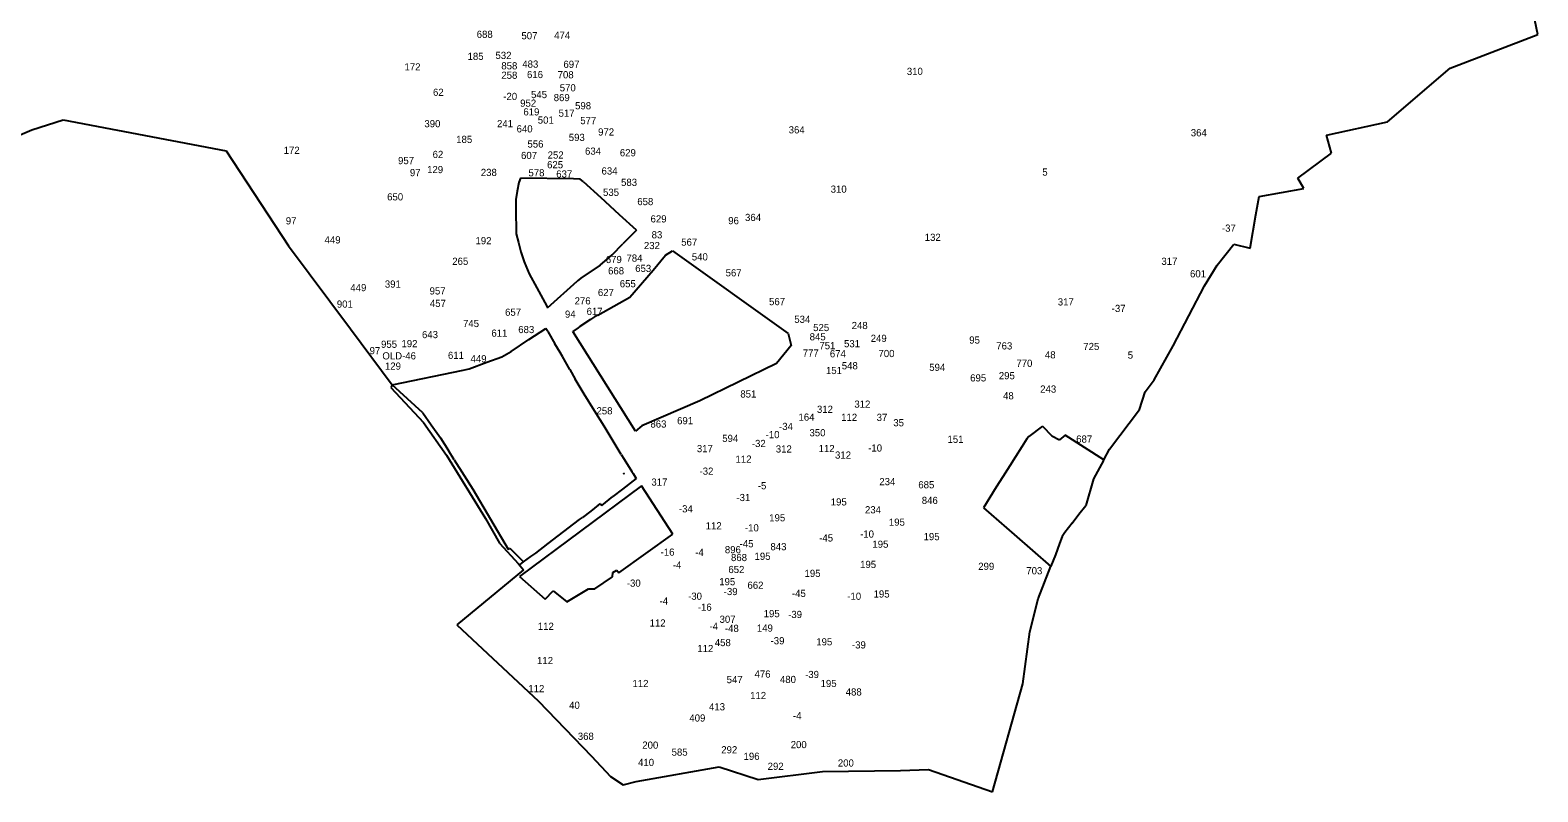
# Model space of a CAD drawing. Extents: x -782977 to -778030, y -975420 to -964838.
# Drawn here: x -780729 to -779276, y -975420 to -974686 of the extents above; entities that cross this region are included whole.
import ezdxf

# ---------------------------------------------------------------- set-up
doc = ezdxf.new("R2010")
doc.units = 0
for name, color, linetype in [('Vrstva 13', 7, 'Continuous'), ('Vrstva 24', 7, 'Continuous'), ('Vrstva 25', 7, 'Continuous')]:
    doc.layers.add(name, color=color, linetype=linetype)

msp = doc.modelspace()

# ---------------------------------------------------------------- linework, layer by layer
at = {"layer": 'Vrstva 13'}
for p, q in [((-779276.15, -974689.93), (-779291.56, -974614.39)), ((-779360.76, -974722.48), (-779276.15, -974689.93)), ((-779420.96, -974774.16), (-779360.76, -974722.48)), ((-780727.54, -974781.83), (-780697.45, -974772.06)), ((-780697.45, -974772.06), (-780540.25, -974801.96)), ((-779479.96, -974787.01), (-779420.96, -974774.16)), ((-780777.37, -974803.19), (-780727.54, -974781.83)), ((-779474.98, -974804.25), (-779479.96, -974787.01)), ((-780540.25, -974801.96), (-780480.25, -974893.51)), ((-779507.54, -974828.24), (-779474.98, -974804.25)), ((-780258.12, -974832.52), (-780260.02, -974840.79)), ((-780256.54, -974828.45), (-780258.12, -974832.52)), ((-780205.46, -974828.92), (-780256.54, -974828.45)), ((-780199.25, -974829.28), (-780205.46, -974828.92)), ((-780196.16, -974831.59), (-780199.25, -974829.28)), ((-780196.16, -974831.59), (-780179.25, -974847.09)), ((-779501.54, -974838.41), (-779507.54, -974828.24)), ((-780261.05, -974848.88), (-780261.22, -974856.8)), ((-780260.02, -974840.79), (-780261.05, -974848.88)), ((-780161.32, -974863.73), (-780179.25, -974847.09)), ((-779548.05, -974863.78), (-779544.88, -974845.91)), ((-779544.88, -974845.91), (-779501.54, -974838.41)), ((-780261.22, -974856.8), (-780261.22, -974865.41)), ((-780144.95, -974878.55), (-780161.32, -974863.73)), ((-779553.44, -974895.73), (-779548.05, -974863.78)), ((-780261.22, -974865.41), (-780260.88, -974874.37)), ((-780260.88, -974874.37), (-780260.71, -974881.95)), ((-780144.95, -974878.55), (-780158.07, -974891.81)), ((-780260.71, -974881.95), (-780258.47, -974890.39)), ((-780258.47, -974890.39), (-780256.23, -974899.51)), ((-780168.47, -974902.2), (-780158.07, -974891.81)), ((-779585.17, -974912.21), (-779569.2, -974891.86)), ((-779569.2, -974891.86), (-779553.44, -974895.73)), ((-780480.25, -974893.51), (-780420.62, -974973.73)), ((-780256.23, -974899.51), (-780253.04, -974909.11)), ((-780179.77, -974912.08), (-780168.47, -974902.2)), ((-780128.94, -974917.07), (-780116.94, -974902.63)), ((-780116.94, -974902.63), (-780110.08, -974898.35)), ((-780110.08, -974898.35), (-779998.78, -974978.05)), ((-780253.04, -974909.11), (-780248.26, -974920.44)), ((-780248.26, -974920.44), (-780241.08, -974933.98)), ((-780179.77, -974912.08), (-780198.49, -974924.83)), ((-780151.43, -974943.18), (-780128.94, -974917.07)), ((-779597.43, -974931.99), (-779585.17, -974912.21)), ((-780241.08, -974933.98), (-780231.26, -974951.83)), ((-780230.57, -974953.29), (-780202.19, -974927.69)), ((-780198.49, -974924.83), (-780202.19, -974927.69)), ((-779627.7, -974989.87), (-779597.43, -974931.99)), ((-780182.13, -974960.29), (-780151.43, -974943.18)), ((-780231.26, -974951.83), (-780230.57, -974953.29)), ((-780189.22, -974964.57), (-780199.35, -974971.3)), ((-780185.39, -974961.96), (-780189.22, -974964.57)), ((-780182.13, -974960.29), (-780185.39, -974961.96)), ((-780420.62, -974973.73), (-780380.36, -975027.54)), ((-780248.66, -974983.75), (-780232.22, -974973.26)), ((-780230.35, -974976.24), (-780232.22, -974973.26)), ((-780230.35, -974976.24), (-780223.44, -974988.04)), ((-780201.16, -974972.53), (-780206.256, -974976.114)), ((-780145.705, -975072.215), (-780206.256, -974976.114)), ((-780199.35, -974971.3), (-780201.16, -974972.53)), ((-779998.78, -974978.05), (-779995.86, -974989.73)), ((-780265.82, -974995.34), (-780248.66, -974983.75)), ((-780218.56, -974996.55), (-780223.44, -974988.04)), ((-779995.86, -974989.73), (-780009.85, -975007.08)), ((-779645.81, -975022.66), (-779627.7, -974989.87)), ((-780306.23, -975011.99), (-780289.25, -975005.87)), ((-780289.25, -975005.87), (-780274.5, -975000.49)), ((-780274.5, -975000.49), (-780265.82, -974995.34)), ((-780216.18, -975000.27), (-780218.56, -974996.55)), ((-780209.04, -975012.94), (-780216.18, -975000.27)), ((-780009.85, -975007.08), (-780083.92, -975043)), ((-780380.36, -975027.54), (-780311.78, -975013.35)), ((-780311.78, -975013.35), (-780306.23, -975011.99)), ((-780209.04, -975012.94), (-780203.9, -975022.23)), ((-780195.28, -975036.66), (-780203.9, -975022.23)), ((-779654.66, -975034.31), (-779645.81, -975022.66)), ((-780380.36, -975027.54), (-780381.79, -975029.98)), ((-780381.79, -975029.98), (-780350.26, -975063.75)), ((-780350.81, -975054.67), (-780380.36, -975027.54)), ((-780185.48, -975052.71), (-780195.28, -975036.66)), ((-779660.17, -975051.23), (-779654.66, -975034.31)), ((-780176.19, -975067.31), (-780185.48, -975052.71)), ((-780083.92, -975043), (-780139.82, -975067.22)), ((-779689.15, -975089.58), (-779660.17, -975051.23)), ((-780350.81, -975054.67), (-780342.75, -975066.05)), ((-780350.26, -975063.75), (-780328.05, -975095.44)), ((-780342.75, -975066.05), (-780333.77, -975078.61)), ((-780159.53, -975094.59), (-780176.19, -975067.31)), ((-780139.82, -975067.22), (-780145.705, -975072.215)), ((-779753.47, -975067.41), (-779766.6, -975077.49)), ((-779753.47, -975067.41), (-779744.49, -975076.59)), ((-780333.77, -975078.61), (-780326.02, -975091.01)), ((-779768.69, -975079.53), (-779773.57, -975087.26)), ((-779766.6, -975077.49), (-779768.69, -975079.53)), ((-779744.49, -975076.59), (-779737.19, -975080.54)), ((-779731.85, -975076.16), (-779737.19, -975080.54)), ((-779694.586, -975099.942), (-779731.85, -975076.16)), ((-780328.05, -975095.44), (-780290.43, -975156.47)), ((-780320.51, -975099.89), (-780326.02, -975091.01)), ((-780159.53, -975094.59), (-780156.63, -975099.15)), ((-779773.57, -975087.26), (-779779.53, -975097.04)), ((-779694.586, -975099.942), (-779689.15, -975089.58)), ((-780320.51, -975099.89), (-780311.12, -975114.84)), ((-780156.63, -975099.15), (-780149.21, -975111.17)), ((-780149.21, -975111.17), (-780148.01, -975113.1)), ((-779785.07, -975105.8), (-779791.79, -975116.39)), ((-779779.53, -975097.04), (-779785.07, -975105.8)), ((-779694.78, -975100.37), (-779704.54, -975118.21)), ((-779694.78, -975100.37), (-779693.82, -975098.61)), ((-780311.12, -975114.84), (-780302.5, -975128.1)), ((-780140.16, -975125.02), (-780257.48, -975212.39)), ((-780145.18, -975117.69), (-780158.48, -975128.11)), ((-780148.01, -975113.1), (-780145.18, -975117.69)), ((-780109.97, -975171.36), (-780140.16, -975125.02)), ((-779791.79, -975116.39), (-779798.1, -975126.17)), ((-779704.54, -975118.21), (-779711.67, -975143.72)), ((-780302.5, -975128.1), (-780268.63, -975185.97)), ((-780178.23, -975143.92), (-780167.57, -975135.33)), ((-780158.48, -975128.11), (-780167.57, -975135.33)), ((-779804.2, -975136.09), (-779810.51, -975146.08)), ((-779798.1, -975126.17), (-779804.2, -975136.09)), ((-780188.78, -975149.25), (-780196.9, -975155.33)), ((-780181.69, -975143.64), (-780188.78, -975149.25)), ((-780179.65, -975142.22), (-780181.69, -975143.64)), ((-780179.65, -975142.22), (-780178.23, -975143.92)), ((-779810.51, -975146.08), (-779781.02, -975171.97)), ((-779725.13, -975160.88), (-779718.54, -975152.19)), ((-779718.54, -975152.19), (-779711.67, -975143.72)), ((-780290.43, -975156.47), (-780276.8, -975180.07)), ((-780220.42, -975173.08), (-780199.79, -975157.42)), ((-780199.79, -975157.42), (-780196.9, -975155.33)), ((-779725.13, -975160.88), (-779732.15, -975169.96)), ((-780276.8, -975180.07), (-780258.5, -975200.01)), ((-780241.82, -975189.73), (-780229.93, -975180.44)), ((-780229.93, -975180.44), (-780220.42, -975173.08)), ((-780161.99, -975208.72), (-780109.97, -975171.36)), ((-779781.02, -975171.97), (-779745.6, -975202.52)), ((-779737.14, -975180.6), (-779741.02, -975191.34)), ((-779734.46, -975173.8), (-779737.14, -975180.6)), ((-779732.15, -975169.96), (-779734.46, -975173.8)), ((-780268.63, -975185.97), (-780266.82, -975185.06)), ((-780266.82, -975185.06), (-780253.83, -975198.23)), ((-780257.11, -975200.61), (-780253.83, -975198.23)), ((-780253.83, -975198.23), (-780246.58, -975193.13)), ((-780246.58, -975193.13), (-780241.82, -975189.73)), ((-779741.02, -975191.34), (-779745.47, -975202.4)), ((-780253.63, -975205.91), (-780317.9, -975259.01)), ((-780258.5, -975200.01), (-780253.63, -975205.91)), ((-780257.48, -975212.39), (-780232.85, -975234.28)), ((-780185.02, -975224.25), (-780167.91, -975212.49)), ((-780167.91, -975212.49), (-780167.71, -975208.41)), ((-780167.71, -975208.41), (-780163.73, -975206.27)), ((-780163.73, -975206.27), (-780161.99, -975208.72)), ((-779757.88, -975233.93), (-779745.47, -975202.4)), ((-780232.85, -975234.28), (-780225.3, -975226.22)), ((-780225.3, -975226.22), (-780212.14, -975236.73)), ((-780212.14, -975236.73), (-780190.99, -975224.05)), ((-780190.99, -975224.05), (-780185.02, -975224.25)), ((-779765.71, -975265.56), (-779757.88, -975233.93)), ((-780317.9, -975259.01), (-780239.2, -975332.45)), ((-779772.57, -975315.67), (-779765.71, -975265.56)), ((-779801.7, -975419.88), (-779772.57, -975315.67)), ((-780239.2, -975332.45), (-780188.15, -975385.55)), ((-780188.15, -975385.55), (-780170.05, -975405.08)), ((-780145.24, -975409.97), (-780065.11, -975395.72)), ((-780065.11, -975395.72), (-780027.71, -975407.86)), ((-780027.71, -975407.86), (-779965.66, -975400.41)), ((-779965.66, -975400.41), (-779890.42, -975399.39)), ((-779890.42, -975399.39), (-779863.52, -975398.32)), ((-779863.52, -975398.32), (-779801.7, -975419.88)), ((-780170.05, -975405.08), (-780157.64, -975413.22)), ((-780157.64, -975413.22), (-780145.24, -975409.97))]:
    msp.add_line(p, q, dxfattribs=at)
at = {"layer": 'Vrstva 25'}
msp.add_circle((-780157.03, -975113.05), 0.175, dxfattribs=at)

# ---------------------------------------------------------------- texts
at = {"layer": 'Vrstva 24'}
for s, p in [('688', (-780298.869, -974693.162)), ('507', (-780255.771, -974694.492)), ('474', (-780224.205, -974694.102)), ('172', (-780368.482, -974724.572)), ('185', (-780307.675, -974714.382)), ('532', (-780280.782, -974713.462)), ('858', (-780275.142, -974723.532)), ('483', (-780254.925, -974721.862)), ('697', (-780215.281, -974722.062)), ('258', (-780275.132, -974732.602)), ('616', (-780250.389, -974731.942)), ('708', (-780220.861, -974732.132)), ('310', (-779884.308, -974728.872)), ('62', (-780341.003, -974749.032)), ('-20', (-780273.279, -974753.015)), ('545', (-780246.525, -974751.232)), ('869', (-780224.665, -974754.122)), ('570', (-780218.841, -974744.712)), ('952', (-780256.999, -974759.492)), ('619', (-780253.909, -974767.912)), ('517', (-780219.953, -974769.152)), ('598', (-780204.069, -974761.992)), ('390', (-780349.281, -974779.292)), ('241', (-780279.288, -974779.282)), ('501', (-780240.007, -974775.802)), ('577', (-780199.055, -974776.322)), ('185', (-780318.625, -974794.442)), ('640', (-780260.414, -974784.272)), ('593', (-780210.129, -974792.522)), ('972', (-780181.855, -974787.282)), ('364', (-779998.201, -974785.232)), ('364', (-779610.621, -974788.012)), ('172', (-780484.932, -974804.942)), ('62', (-780341.363, -974808.922)), ('607', (-780256.147, -974809.912)), ('556', (-780249.959, -974798.862)), ('252', (-780230.512, -974809.512)), ('634', (-780194.481, -974805.762)), ('629', (-780160.925, -974807.282)), ('957', (-780374.685, -974814.872)), ('97', (-780363.269, -974826.482)), ('129', (-780346.662, -974823.522)), ('238', (-780294.912, -974826.272)), ('578', (-780248.999, -974826.632)), ('625', (-780231.029, -974818.812)), ('637', (-780222.235, -974827.772)), ('634', (-780178.561, -974824.862)), ('5', (-779753.75, -974825.952)), ('583', (-780159.742, -974835.822)), ('310', (-779957.718, -974842.382)), ('650', (-780385.191, -974849.812)), ('535', (-780177.142, -974845.442)), ('658', (-780144.099, -974854.382)), ('629', (-780131.315, -974871.062)), ('364', (-780040.251, -974869.652)), ('97', (-780482.869, -974872.942)), ('96', (-780056.459, -974872.752)), ('-37', (-779580.614, -974879.965)), ('449', (-780445.515, -974891.272)), ('192', (-780300.051, -974892.082)), ('232', (-780137.742, -974896.742)), ('83', (-780130.276, -974886.392)), ('567', (-780101.765, -974893.442)), ('132', (-779867.065, -974888.812)), ('265', (-780322.429, -974911.932)), ('679', (-780174.451, -974910.222)), ('784', (-780154.542, -974908.862)), ('540', (-780091.547, -974907.662)), ('317', (-779638.983, -974911.942)), ('668', (-780172.255, -974921.122)), ('653', (-780146.109, -974918.782)), ('567', (-780058.955, -974923.022)), ('601', (-779611.383, -974923.982)), ('449', (-780420.645, -974937.302)), ('391', (-780387.421, -974933.872)), ('957', (-780344.265, -974940.472)), ('627', (-780182.065, -974941.992)), ('655', (-780160.969, -974933.532)), ('901', (-780433.663, -974953.162)), ('457', (-780343.982, -974952.472)), ('276', (-780204.525, -974950.082)), ('567', (-780017.125, -974950.812)), ('317', (-779738.823, -974951.062)), ('-37', (-779686.844, -974957.365)), ('745', (-780312.071, -974971.912)), ('657', (-780271.535, -974961.012)), ('94', (-780213.815, -974962.862)), ('617', (-780192.929, -974960.222)), ('534', (-779992.785, -974967.832)), ('643', (-780351.591, -974982.592)), ('611', (-780284.715, -974981.172)), ('683', (-780258.839, -974977.712)), ('845', (-779977.975, -974984.692)), ('525', (-779974.592, -974975.782)), ('248', (-779937.475, -974973.832)), ('249', (-779919.141, -974986.222)), ('97', (-780402.089, -974998.072)), ('955', (-780391.079, -974991.902)), ('192', (-780371.391, -974991.282)), ('777', (-779984.652, -975000.352)), ('751', (-779968.592, -974993.232)), ('674', (-779958.518, -975001.032)), ('531', (-779944.845, -974991.332)), ('700', (-779911.633, -975000.832)), ('95', (-779824.163, -974987.812)), ('763', (-779798.115, -974993.482)), ('48', (-779751.259, -975002.092)), ('725', (-779714.239, -974994.032)), ('OLD-46', (-780389.804, -975003.085)), ('129', (-780387.322, -975012.952)), ('611', (-780326.575, -975002.592)), ('449', (-780304.845, -975005.882)), ('548', (-779946.995, -975012.612)), ('594', (-779862.711, -975014.162)), ('770', (-779778.748, -975010.262)), ('5', (-779671.41, -975002.342)), ('151', (-779962.279, -975017.192)), ('695', (-779823.245, -975024.312)), ('295', (-779795.649, -975022.172)), ('851', (-780044.805, -975039.812)), ('48', (-779791.569, -975041.542)), ('243', (-779755.785, -975035.082)), ('258', (-780183.422, -975056.052)), ('312', (-779970.945, -975054.582)), ('312', (-779934.905, -975049.622)), ('863', (-780131.449, -975068.752)), ('691', (-780105.718, -975065.542)), ('-34', (-780007.48, -975071.115)), ('164', (-779988.735, -975062.122)), ('112', (-779947.619, -975062.312)), ('37', (-779913.393, -975062.412)), ('35', (-779897.376, -975067.532)), ('594', (-780062.211, -975082.642)), ('-32', (-780033.686, -975087.525)), ('-10', (-780020.382, -975078.975)), ('350', (-779978.135, -975077.162)), ('151', (-779845.119, -975083.512)), ('687', (-779721.075, -975083.282)), ('317', (-780086.683, -975092.472)), ('112', (-780049.409, -975102.592)), ('312', (-780010.615, -975092.822)), ('112', (-779969.359, -975092.412)), ('312', (-779953.525, -975098.722)), ('-10', (-779921.542, -975091.915)), ('-32', (-780084.116, -975114.215)), ('317', (-780130.533, -975124.752)), ('-5', (-780027.96, -975128.245)), ('234', (-779910.815, -975124.292)), ('685', (-779873.249, -975127.322)), ('-31', (-780048.58, -975139.625)), ('195', (-779957.661, -975143.852)), ('846', (-779869.911, -975142.412)), ('-34', (-780103.97, -975150.525)), ('195', (-780016.941, -975159.142)), ('234', (-779924.655, -975151.452)), ('112', (-780078.189, -975166.852)), ('-10', (-780040.392, -975168.835)), ('-10', (-779929.362, -975174.835)), ('195', (-779901.631, -975163.362)), ('896', (-780059.695, -975189.892)), ('-45', (-780045.42, -975184.145)), ('843', (-780015.775, -975186.982)), ('-45', (-779968.76, -975178.605)), ('195', (-779917.511, -975184.602)), ('195', (-779868.171, -975177.332)), ('-16', (-780121.626, -975192.235)), ('-4', (-780109.874, -975204.725)), ('-4', (-780088.264, -975192.525)), ('868', (-780053.789, -975197.462)), ('195', (-780031.091, -975196.262)), ('195', (-779929.361, -975204.112)), ('652', (-780056.309, -975209.012)), ('195', (-779982.901, -975212.722)), ('299', (-779815.485, -975205.972)), ('703', (-779769.161, -975210.212)), ('-30', (-780154.179, -975222.145)), ('195', (-780065.121, -975220.742)), ('-39', (-780060.814, -975230.235)), ('662', (-780037.925, -975224.182)), ('-45', (-779995.03, -975232.055)), ('195', (-779916.361, -975232.612)), ('-4', (-780122.624, -975239.375)), ('-30', (-780095.139, -975234.745)), ('-16', (-780085.756, -975245.325)), ('-10', (-779941.702, -975234.775)), ('112', (-780239.979, -975263.752)), ('112', (-780132.239, -975260.592)), ('307', (-780064.791, -975256.982)), ('195', (-780022.291, -975251.542)), ('-39', (-779998.694, -975252.325)), ('-4', (-780074.524, -975263.705)), ('-48', (-780059.66, -975265.805)), ('149', (-780028.875, -975265.482)), ('-39', (-780015.634, -975277.685)), ('112', (-780086.259, -975285.172)), ('458', (-780069.395, -975279.432)), ('195', (-779971.621, -975278.712)), ('-39', (-779937.204, -975281.695)), ('112', (-780240.689, -975296.762)), ('112', (-780148.729, -975318.882)), ('547', (-780057.972, -975315.122)), ('476', (-780031.088, -975309.772)), ('480', (-780006.607, -975314.982)), ('-39', (-779982.374, -975310.195)), ('195', (-779967.421, -975318.872)), ('112', (-780249.119, -975323.802)), ('112', (-780035.369, -975330.462)), ('488', (-779943.225, -975327.022)), ('40', (-780209.791, -975339.832)), ('413', (-780074.968, -975341.332)), ('-4', (-779994.054, -975349.985)), ('409', (-780093.914, -975352.152)), ('368', (-780201.439, -975369.742)), ('200', (-780139.297, -975378.282)), ('200', (-779996.237, -975377.782)), ('585', (-780111.022, -975385.062)), ('292', (-780063.179, -975382.772)), ('196', (-780041.669, -975389.042)), ('410', (-780143.351, -975394.952)), ('292', (-780018.459, -975398.672)), ('200', (-779950.787, -975395.512))]:
    msp.add_text(s, height=6.912, dxfattribs=at).set_placement(p)

doc.saveas('drawing.dxf')
